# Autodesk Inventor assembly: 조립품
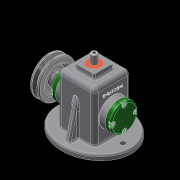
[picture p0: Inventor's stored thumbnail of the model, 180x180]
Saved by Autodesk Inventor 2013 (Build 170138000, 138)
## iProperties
Created: 2017-07
Part Number: 조립품
Document SubType Name: Assembly
Designer: elite
Author: elite
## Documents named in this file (16)
- C:\Users\elite\Desktop\470708V1024\조립품.iam
- C:\Users\elite\Desktop\470708V1024\본체.ipt
- C:\Users\elite\Desktop\470708V1024\베어링 12 x 32 x 10.ipt
- C:\Users\elite\Desktop\470708V1024\편심축.ipt
- C:\Users\elite\Desktop\470708V1024\슬라이드.ipt
- C:\Users\elite\Desktop\470708V1024\부시.ipt
- C:\Users\elite\Desktop\470708V1024\고정핀 1.2 x  8.ipt
- C:\Users\elite\Desktop\470708V1024\링크.ipt
- C:\Users\elite\Desktop\470708V1024\핀 5 x 18.ipt
- C:\Users\elite\Desktop\470708V1024\뒤커버.ipt
- C:\Users\elite\Desktop\470708V1024\앞커버.ipt
- C:\Users\elite\Desktop\470708V1024\볼트 M4 x 12.ipt
- C:\Users\elite\Desktop\470708V1024\오일실 12 25 7.ipt
- C:\Users\elite\Desktop\470708V1024\V벨트풀리.ipt
- C:\Users\elite\Desktop\470708V1024\멈춤나사 M3x8.ipt
- C:\Users\elite\Desktop\470708V1024\키 4 x 4 x 10.ipt
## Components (3 placed, 3 different names)
1. 고정핀 1.2 x  8:1
2. 핀 5 x 18:1
3. V벨트풀리:1
